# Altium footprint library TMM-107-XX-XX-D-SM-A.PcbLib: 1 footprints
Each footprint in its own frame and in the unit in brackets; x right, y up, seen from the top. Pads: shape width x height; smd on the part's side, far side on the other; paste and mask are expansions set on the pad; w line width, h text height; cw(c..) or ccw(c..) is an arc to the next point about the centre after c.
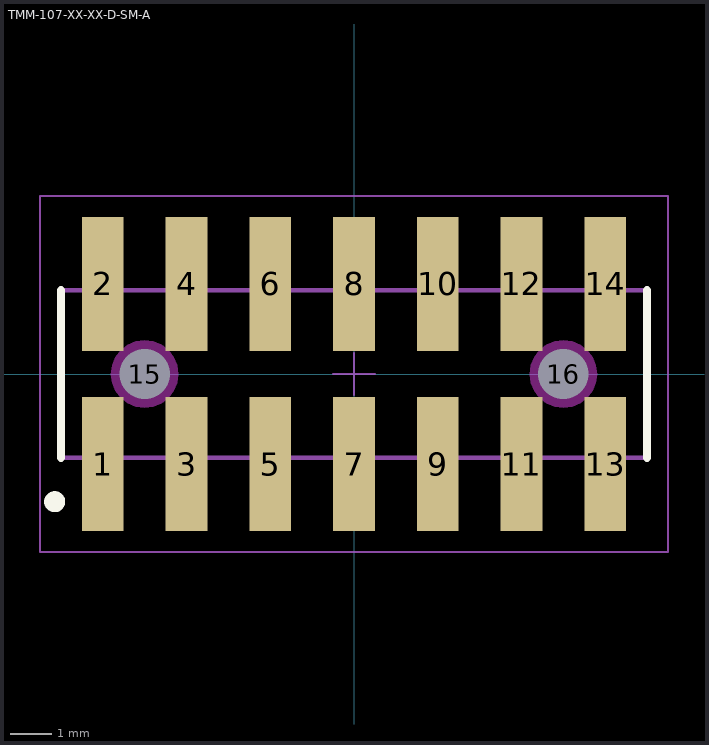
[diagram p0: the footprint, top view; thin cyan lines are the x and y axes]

## TMM-107-XX-XX-D-SM-A [mm] "2.00mm pitch, 14 pin, terminal strip; double row, w/alignment pins, SMT"
height 2.77
pads (16):
  rect 1x3.2 smd mask+0: 1(-6,-2.15) 2(-6,2.15) 3(-4,-2.15) 4(-4,2.15) 5(-2,-2.15) 6(-2,2.15) 7(0,-2.15) 8(0,2.15) 9(2,-2.15) 10(2,2.15) 11(4,-2.15) 12(4,2.15) 13(6,-2.15) 14(6,2.15)
  round 1 hole 1.2 unplated mask+0: 15(-5,0) 16(5,0)
Top Overlay:
  circle w0.25: c-7.15,-3.05 r0.125
  lines w0.2: -7,-2 -7,2 ; 7,-2 7,2
Keep-Out Layer:
  pour cut-out: 5.807,0 5.779,0.209 5.699,0.403 5.571,0.571 5.403,0.699 5.209,0.779 5,0.807 4.791,0.779 4.597,0.699 4.429,0.571 4.301,0.403 4.221,0.209 4.193,0 4.221,-0.209 4.301,-0.403 4.429,-0.571 4.597,-0.699 4.791,-0.779 5,-0.807 5.209,-0.779 5.403,-0.699 5.571,-0.571 5.699,-0.403 5.779,-0.209
  pour cut-out: -4.193,0 -4.221,0.209 -4.301,0.403 -4.429,0.571 -4.597,0.699 -4.791,0.779 -5,0.807 -5.209,0.779 -5.403,0.699 -5.571,0.571 -5.699,0.403 -5.779,0.209 -5.807,0 -5.779,-0.209 -5.699,-0.403 -5.571,-0.571 -5.403,-0.699 -5.209,-0.779 -5,-0.807 -4.791,-0.779 -4.597,-0.699 -4.429,-0.571 -4.301,-0.403 -4.221,-0.209
Mechanical 12:
  lines w0.001: -7,-2 -7,2 7,2 7,-2 -7,-2
Mechanical 13:
  lines w0.1: -7,-2 -7,2 7,2 7,-2 -7,-2
  text ".Designator" at 0,-0.127 h1.52
Mechanical 15:
  lines w0.05: -0.5,0 0.5,0 ; 0,-0.5 0,0.5 ; -7.5,-4.25 -7.5,4.25 7.5,4.25 7.5,-4.25 -7.5,-4.25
